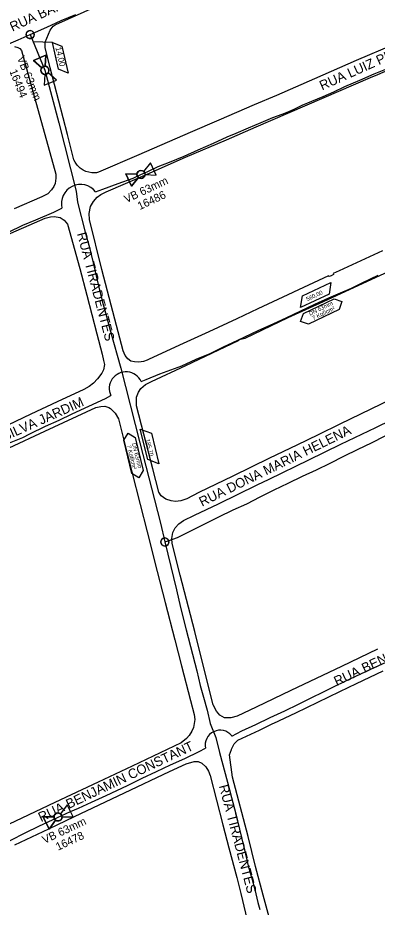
# Model space of a CAD drawing. Extents: x 656692 to 673945, y 7585994 to 7599066.
# Drawn here: x 668995 to 669264, y 7594792 to 7595459 of the extents above; entities that cross this region are included whole.
import ezdxf

# ---------------------------------------------------------------- set-up
doc = ezdxf.new("R2010")
doc.units = 0
for name, color, linetype in [('LOGRADOURO', 7, 'Continuous'), ('LOGRADOURO_TEXTO', 7, 'Continuous'), ('SIMBOLO', 7, 'Continuous'), ('TEXTO', 7, 'Continuous'), ('TUBO_PEAD_GN_63', 7, 'Continuous'), ('VALVULA_PEAD_63', 7, 'Continuous')]:
    doc.layers.add(name, color=color, linetype=linetype)

# ---------------------------------------------------------------- blocks, each defined once
blk = doc.blocks.new('VALVULA_PEAD_DN_16')
at = {"layer": 'VALVULA_PEAD_63'}
for points in [[(-0.0374, 0.0187), (-0.1395, 0.0698), (-0.1395, -0.0698), (-0.0374, -0.0187)], [(-0.0374, -0.0187), (-0.1395, -0.0698), (-0.1395, 0.0698), (-0.0374, 0.0187)], [(0.0374, -0.0187), (0.1395, -0.0698), (0.1395, 0.0698), (0.0374, 0.0187)], [(0.0374, -0.0187), (0.1395, -0.0698), (0.1395, 0.0698), (0.0374, 0.0187)]]:
    blk.add_lwpolyline(points, dxfattribs=at)
blk.add_circle((0, 0), 0.0419, dxfattribs=at)
for start, end in [(90, 270), (153.43495, 206.56505), (270, 90), (333.43495, 26.56505)]:
    blk.add_arc((0, 0), 0.0419, start, end, dxfattribs=at)
blk = doc.blocks.new('INTERLIGACAO_9')
at = {"layer": 'SIMBOLO'}
blk.add_circle((0, 0), 4.19, dxfattribs=at)
for start, end in [(0, 180), (180, 0)]:
    blk.add_arc((0, 0), 4.19, start, end, dxfattribs=at)

msp = doc.modelspace()

# ---------------------------------------------------------------- linework, layer by layer
at = {"layer": 'LOGRADOURO'}
for points in [[(669276.93, 7595439.08), (669248.79, 7595427.06), (669217.44, 7595413.27), (669188.92, 7595400.91), (669172.33, 7595393.89), (669145.63, 7595382.28), (669124.22, 7595372.99), (669085.62, 7595356.36), (669055.47, 7595343.31), (669053.98, 7595342.86), (669050.49, 7595342.77), (669046.1, 7595343.89), (669043.94, 7595344.88), (669041.78, 7595346.29), (669039.52, 7595348.51), (669037.99, 7595350.69), (669036.95, 7595352.57), (669032.15, 7595371.68), (669019.18, 7595421.63), (669015.53, 7595436.81), (669015.49, 7595440.82), (669019.37, 7595449.85), (669021.56, 7595452.78), (669022.98, 7595453.76), (669023.52, 7595453.96), (669054.3, 7595467.67)], [(669048.62, 7595307.85), (669048.61, 7595312.37), (669049.48, 7595317.48), (669051.65, 7595321.37), (669054.37, 7595324.45), (669057.28, 7595326.68), (669061.15, 7595328.65), (669091.88, 7595341.82), (669120.69, 7595354.48), (669151.36, 7595367.53), (669173.62, 7595377.26), (669235.76, 7595404.08), (669259.41, 7595414.39), (669264.95, 7595416.65), (669301.66, 7595432.47), (669329.46, 7595444.44), (669360.9, 7595458.11), (669386.36, 7595469.04)], [(668992.52, 7595437.56), (668995.03, 7595436.8), (668996.47, 7595435.98), (668997.78, 7595434.66), (669023.38, 7595341.89), (669023.57, 7595338.84), (669023.1, 7595334.8), (669021.91, 7595332.5), (669020.3, 7595329.96), (669017.39, 7595327.16), (669013.1, 7595324.83), (668992.3, 7595315.82)], [(668971.82, 7595289.9), (669007.48, 7595305.37), (669015.52, 7595308.85), (669019.59, 7595309.94), (669022.19, 7595310.09), (669026.76, 7595309.36), (669029.69, 7595307.33), (669032.13, 7595304.43)], [(669268.34, 7595284.32), (669236.07, 7595269.37), (669231.5, 7595267.23), (669231.62, 7595266.67), (669229.87, 7595265.48), (669228.38, 7595265.05), (669227.96, 7595265.58), (669175, 7595240.8), (669159.27, 7595233.45), (669138.14, 7595223.61), (669116.3, 7595213.5), (669092.89, 7595202.85), (669091.99, 7595202.31), (669089.27, 7595201.25), (669085.71, 7595200.95), (669082.44, 7595201.02), (669079.74, 7595201.63), (669077.41, 7595203.27), (669075.41, 7595205.87), (669074.06, 7595209.41), (669067.72, 7595233.15), (669058.03, 7595270.32), (669048.62, 7595307.85)], [(669032.13, 7595304.43), (669041.56, 7595271.1), (669046.77, 7595251.16), (669054.26, 7595222.15), (669058.16, 7595206.89), (669059.35, 7595202.04), (669059.87, 7595199.13), (669059.14, 7595195.06), (669058.09, 7595192.56), (669054.82, 7595188.46), (669051.81, 7595185.21), (669048.53, 7595182.63), (669044.61, 7595180.26), (669024.61, 7595170.97), (669004.76, 7595161.75), (668981.67, 7595150.9)], [(669283.01, 7595176.92), (669236.42, 7595154.36), (669220.27, 7595146.44), (669204.26, 7595138.66), (669183.8, 7595128.75), (669156.25, 7595115.36), (669130.8, 7595103.01), (669121.64, 7595098.44), (669117.13, 7595096.74), (669113.2, 7595096.42), (669110.01, 7595096.78), (669106.08, 7595098.09), (669102.39, 7595100.65), (669100.84, 7595103.3), (669096.22, 7595120.9), (669089.42, 7595146.95), (669083.91, 7595168.08), (669084.05, 7595174.66), (669085.61, 7595178.44), (669087.31, 7595181.2), (669090.63, 7595184.06), (669095.11, 7595186.39), (669120.86, 7595198.24), (669160.43, 7595216.99), (669160.95, 7595217.63), (669161.88, 7595218.06), (669165.42, 7595218.93), (669197.73, 7595234.22), (669224.1, 7595246.29), (669257.18, 7595261.61), (669292.43, 7595277.9)], [(668988.53, 7595136.48), (669015.31, 7595149), (669053.43, 7595166.81), (669057.16, 7595167.67), (669060.21, 7595167.79), (669063.26, 7595166.96), (669064.58, 7595166.12), (669067.94, 7595162.52), (669070.37, 7595158.34), (669077.72, 7595129.39), (669080.51, 7595118.52), (669086.8, 7595093.99), (669091.97, 7595073.59), (669099.42, 7595043.77), (669105.39, 7595020.61), (669112.81, 7594992.67), (669117.79, 7594973.17), (669124.52, 7594947.02), (669127.2, 7594936.59), (669127.68, 7594932.97), (669126.61, 7594926.87), (669125.45, 7594924.09), (669123.56, 7594920.89), (669121.41, 7594918.57), (669117.58, 7594915.47), (669080.67, 7594897.9), (669055.26, 7594885.96), (669022.85, 7594870.61), (668983.2, 7594851.91)], [(669264.78, 7594985.51), (669237.61, 7594972.69), (669199.84, 7594954.56), (669173.61, 7594942.11), (669159.39, 7594935.35), (669154.62, 7594934.02), (669150.07, 7594934.23), (669146.45, 7594936.16), (669143.91, 7594939.22), (669141.58, 7594943.95), (669135.33, 7594968.63), (669127.67, 7594998.76), (669116.8, 7595041.17), (669110.69, 7595064.77), (669110.41, 7595068.49), (669111.14, 7595073.07), (669113.09, 7595076.73), (669115.71, 7595079.54), (669119.29, 7595082.02), (669127.47, 7595085.99), (669145.37, 7595094.61), (669174.55, 7595108.83), (669183.37, 7595113.12), (669213.31, 7595127.66), (669237.11, 7595139.41), (669263.53, 7595151.91), (669298.24, 7595168.94)], [(669184.22, 7594781.81), (669178.95, 7594801.25), (669173.15, 7594822.7), (669167.67, 7594845.07), (669155.93, 7594889.64), (669153.83, 7594906.46), (669155.17, 7594910.47), (669155.21, 7594910.67), (669157.32, 7594914.51), (669159.93, 7594917.3), (669176.34, 7594924.97), (669186.25, 7594929.82), (669187, 7594930.17), (669203.53, 7594937.84), (669236.54, 7594953.87), (669248.94, 7594959.78), (669269.02, 7594969.38)], [(668992.86, 7594838.88), (669018.19, 7594850.91), (669037.46, 7594860.04), (669055.94, 7594868.84), (669074.92, 7594877.89), (669108.66, 7594893.79), (669121.34, 7594899.71), (669127.18, 7594901.4), (669130.32, 7594901.28), (669132.87, 7594900.13), (669135.94, 7594897.43), (669138, 7594894.08), (669139.33, 7594890.9), (669144.1, 7594872.28), (669148.75, 7594853.96), (669153.24, 7594836.74), (669159.15, 7594814.37), (669162.27, 7594802.36), (669167.88, 7594778.21)]]:
    msp.add_lwpolyline(points, dxfattribs=at)
at = {"layer": 'SIMBOLO'}
for points in [[(669207.06, 7595231.37), (669209.13, 7595237.27), (669232.15, 7595248.33), (669238.05, 7595246.26), (669235.98, 7595240.36), (669212.96, 7595229.3), (669207.06, 7595231.37)], [(669077.7, 7595147.61), (669083.04, 7595144.35), (669089.04, 7595119.53), (669085.78, 7595114.19), (669080.44, 7595117.45), (669074.44, 7595142.27), (669077.7, 7595147.61)]]:
    msp.add_lwpolyline(points, dxfattribs=at)
at = {"layer": 'TEXTO'}
msp.add_line((669020.89, 7595440.62), (669006.6, 7595441.08), dxfattribs=at)
for points in [[(669028.07, 7595437.72), (669032.77, 7595417.67), (669025.62, 7595420.44), (669020.89, 7595440.62), (669028.07, 7595437.72)], [(669208.51, 7595250.62), (669229.8, 7595260.59), (669228.39, 7595251.94), (669206.97, 7595241.91), (669208.51, 7595250.62)], [(669095.11, 7595147.52), (669100.8, 7595124.72), (669092.59, 7595127.77), (669086.86, 7595150.71), (669095.11, 7595147.52)]]:
    msp.add_lwpolyline(points, dxfattribs=at)
at = {"layer": 'TUBO_PEAD_GN_63'}
for points in [[(669004.26, 7595446.49), (669005.97, 7595447.26), (669016.83, 7595452.17), (669027.52, 7595456.94), (669038.38, 7595461.65)], [(668840.32, 7595373.73), (668840.36, 7595373.75), (668848.75, 7595377.25), (668859.32, 7595382.09), (668870.21, 7595387.08), (668880.98, 7595391.75), (668892.22, 7595396.65), (668906.3, 7595402.81), (668919.21, 7595408.53), (668929.89, 7595413.58), (668940.66, 7595418.62), (668951.23, 7595423.75), (668962.11, 7595428.32), (668972.67, 7595432.89), (668984.21, 7595437.92), (668995.22, 7595442.46), (669004.26, 7595446.49)], [(669004.26, 7595446.49), (669015.32, 7595419.69), (669025.83, 7595380.26), (669038.69, 7595329.03), (669039.72, 7595320.82), (669045.56, 7595298.31), (669048.62, 7595286.9), (669051.43, 7595275.29), (669052.79, 7595269.88), (669055.39, 7595258.06), (669058.33, 7595246.77), (669061.49, 7595235.13), (669064.48, 7595223.85), (669072.26, 7595196.32), (669086.59, 7595140.39), (669102.04, 7595080.18), (669105.28, 7595065.99), (669107.43, 7595056.87), (669113.98, 7595030.05), (669116.98, 7595016.93), (669121.34, 7595000.09), (669129.19, 7594969.48), (669131.64, 7594958.27), (669134.16, 7594949.54), (669136.98, 7594939.77), (669139.17, 7594929.87), (669143.54, 7594919.33), (669146.29, 7594908.15), (669152.3, 7594885.96), (669155.22, 7594874.51), (669158.42, 7594862.1), (669162.57, 7594845.48), (669164.96, 7594835.17), (669167.77, 7594823.18), (669170.76, 7594812.91), (669172.63, 7594805.4), (669175.07, 7594795.66), (669176.43, 7594790.43)], [(669087.25, 7595341.54), (669092.56, 7595343.91), (669100.23, 7595347.57), (669108.61, 7595350.8), (669119.75, 7595355.38), (669130.18, 7595360.04), (669141.83, 7595365.11), (669152.09, 7595369.73), (669158.72, 7595372.53), (669167.98, 7595376.61), (669177.37, 7595380.59), (669186.3, 7595384.29), (669193.33, 7595386.84), (669197.73, 7595388.59), (669202.7, 7595390.82), (669208.3, 7595393.44), (669215.45, 7595396.51), (669224.04, 7595400.15), (669231.93, 7595403.59), (669240.22, 7595407.48), (669251.37, 7595412.3), (669262.25, 7595417.09), (669272.2, 7595421.13)], [(669053.35, 7595328.5), (669058.78, 7595330.48), (669070.16, 7595334.74), (669081.38, 7595338.93), (669087.21, 7595341.53)], [(668882.05, 7595252.26), (668887.54, 7595254.73), (668898.11, 7595259.44), (668910.02, 7595264.54), (668919.25, 7595268.72), (668929.43, 7595273.21), (668940.37, 7595277.91), (668951.11, 7595282.51), (668961.3, 7595286.76), (668971.88, 7595291.25), (668982.68, 7595296), (668988.03, 7595298.36), (668998.79, 7595303.61), (669008.5, 7595307.55), (669021.94, 7595313.31), (669028.08, 7595316.3)], [(669087.49, 7595186.27), (669091.12, 7595187.96), (669101.57, 7595192.04), (669118.08, 7595198.18), (669128.61, 7595202.97), (669139.22, 7595207.44), (669149.15, 7595212.24), (669159.88, 7595217.21), (669175.77, 7595224.9), (669186.43, 7595229.54), (669196.8, 7595234.36), (669207.32, 7595239.38), (669217.61, 7595244.34), (669228.11, 7595249.09), (669237.01, 7595252.85), (669245.22, 7595256.31), (669253.26, 7595260.31), (669265.22, 7595266.2)], [(668914.82, 7595106.62), (668918.25, 7595108.27), (668928.88, 7595112.72), (668939.67, 7595117.8), (668950.77, 7595122.84), (668957.9, 7595125.81), (668964.93, 7595129.21), (668982.74, 7595137.08), (668988.79, 7595140.45), (668998.84, 7595144.42), (669004.12, 7595147.09), (669015.63, 7595152.86), (669025.91, 7595157.37), (669035.74, 7595162.04), (669060.66, 7595173.55), (669064.75, 7595175.74)], [(669105.28, 7595065.99), (669107.73, 7595066.95), (669114.72, 7595069.42), (669124.69, 7595074.42), (669135.32, 7595079.67), (669145.83, 7595084.85), (669156.45, 7595090.16), (669166.62, 7595094.59), (669176.83, 7595099.81), (669187.29, 7595105.05), (669197.71, 7595110), (669208.49, 7595115.32), (669218.84, 7595120.04), (669229.15, 7595125.14), (669239.54, 7595130.24), (669250.13, 7595135.51), (669260.13, 7595140.38), (669270.45, 7595145.59)], [(669155.47, 7594920.49), (669162.96, 7594924.28), (669173.48, 7594929.21), (669184.15, 7594934.3), (669195.1, 7594939.28), (669205.47, 7594944.5), (669233.72, 7594958.25), (669244.25, 7594963.29), (669260.22, 7594970.97), (669281.59, 7594980.72)], [(668975.62, 7594835.23), (668978.96, 7594836.83), (668989.31, 7594842.1), (669000.91, 7594848.18), (669010.84, 7594852.92), (669021.4, 7594858.01), (669034.58, 7594863.81), (669040.56, 7594866.42), (669050.3, 7594870.92), (669061.32, 7594875.99), (669077.24, 7594883.35), (669088.13, 7594888.79), (669099.09, 7594894), (669109.57, 7594898.93), (669120.18, 7594903.68), (669130.89, 7594908.93), (669135.72, 7594911.31)]]:
    msp.add_lwpolyline(points, dxfattribs=at)
for centre, radius, start, end in [((669041.99, 7595319.75), 14.34, 37.61921, 193.90707), ((669076.09, 7595181.06), 12.53, 24.55527, 205.10417), ((669146.67, 7594913.65), 11.19, 38.9322, 192.0313)]:
    msp.add_arc(centre, radius, start, end, dxfattribs=at)

# ---------------------------------------------------------------- block references
at = {"layer": 'SIMBOLO', "xscale": 0.7229249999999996, "yscale": 0.7229249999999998, "rotation": 166.312122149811}
for p in [(669004.21, 7595446.47), (669105.23, 7595065.97)]:
    msp.add_blockref('INTERLIGACAO_9', p, dxfattribs=at)
at = {"layer": 'VALVULA_PEAD_63'}
for p, xscale, yscale, rotation in [((669015.32, 7595419.69), 72.29249999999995, 72.29249999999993, -66.94801256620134), ((669087.37, 7595341.59), 72.29249999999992, 72.29249999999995, 23.827974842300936), ((669025.16, 7594859.82), 72.29249999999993, 72.29249999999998, 26.837976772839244)]:
    msp.add_blockref('VALVULA_PEAD_DN_16', p, dxfattribs=dict(at, xscale=xscale, yscale=yscale, rotation=rotation))

# ---------------------------------------------------------------- texts
for s, rotation, p in [('VB 63mm', 292.04801, (668994.23, 7595428.89)), ('16494', 292.04801, (668988.51, 7595419.09)), ('VB 63mm', 25.04801, (669076.35, 7595320.03)), ('16486', 25.04801, (669086.44, 7595314.83)), ('VB 63mm', 25.04801, (669015.02, 7594839.59)), ('16478', 25.04801, (669025.11, 7594834.39))]:
    msp.add_text(s, height=6, rotation=rotation).set_placement(p)
at = {"layer": 'LOGRADOURO_TEXTO'}
for s, rotation, p in [('RUA BARÃO DE CATAGUÁSES', 24.30453, (668990.93, 7595448.6)), ('RUA LUIZ PERRY', 24.10472, (669223.17, 7595404.51)), ('RUA TIRADENTES', 284.88447, (669039.26, 7595297.22)), ('RUA SILVA JARDIM', 24.10472, (668964.13, 7595132.15)), ('RUA DONA MARIA HELENA', 26.05221, (669133.11, 7595092.39)), ('RUA BENJAMIN CONSTANT', 25.36438, (669234.13, 7594957.84)), ('RUA BENJAMIN CONSTANT', 25.36438, (669012.4, 7594855.87)), ('RUA TIRADENTES', 284.88447, (669145.71, 7594883.05))]:
    msp.add_text(s, height=7.2, rotation=rotation, dxfattribs=at).set_placement(p)
at = {"layer": 'TEXTO'}
for s, height, rotation, p in [('14,00', 4.447, 283.19761, (669023.15, 7595436.71)), ('560,00', 3.113, 25.08912, (669212.07, 7595246.43)), ('DN 63mm', 3.113, 25.66002, (669214.14, 7595235.63)), ('7 Kgf/cm²', 3.113, 25.66002, (669216.58, 7595232.22)), ('7 Kgf/cm²', 3.113, 283.59744, (669076.76, 7595138.19)), ('DN 63mm', 3.113, 283.59744, (669080.6, 7595139.87)), ('185,70', 3.113, 284.02005, (669090.71, 7595142.77))]:
    msp.add_text(s, height=height, rotation=rotation, dxfattribs=at).set_placement(p)

doc.saveas('drawing.dxf')
